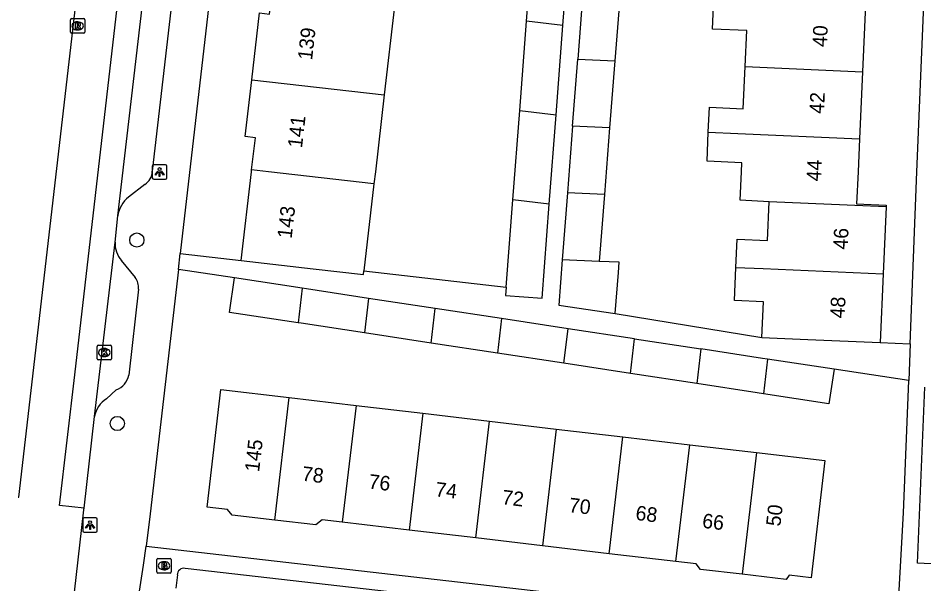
# Model space of a CAD drawing. Extents: x 162250 to 162654, y 380744 to 381605.
# Drawn here: x 162274.7 to 162337.1, y 380971.6 to 381010.6 of the extents above; entities that cross this region are included whole.
import ezdxf

# ---------------------------------------------------------------- set-up
doc = ezdxf.new("R2010")
doc.units = 0
for name, color, linetype in [('IMGEO_Boom', 7, 'Continuous'), ('IMGEO_Brandkraan', 7, 'Continuous'), ('IMGEO_Kolk', 7, 'Continuous'), ('IMGEO_Lichtpunt', 7, 'Continuous'), ('IMGEO_Pand', 7, 'Continuous'), ('IMGEO_Pand_nummerreeks', 7, 'Continuous'), ('IMGEO_Rijbaan_lokaal_gesloten', 7, 'Continuous'), ('IMGEO_Rioolput', 7, 'Continuous'), ('IMGEO_Voetpad_open', 7, 'Continuous')]:
    doc.layers.add(name, color=color, linetype=linetype)

msp = doc.modelspace()

# ---------------------------------------------------------------- linework, layer by layer
at = {"layer": 'IMGEO_Boom'}
for centre in [(162282.839, 380995.291), (162281.491, 380982.662)]:
    msp.add_circle(centre, 0.489, dxfattribs=at)
at = {"layer": 'IMGEO_Brandkraan'}
for p, q in [((162284.213, 380972.443), (162284.213, 380973.295)), ((162284.288, 380973.369), (162285.14, 380973.369)), ((162285.214, 380973.295), (162285.214, 380972.443)), ((162284.701, 380973.149), (162284.726, 380973.149)), ((162285.14, 380972.369), (162284.288, 380972.369)), ((162284.724, 380972.589), (162284.699, 380972.589))]:
    msp.add_line(p, q, dxfattribs=at)
for points in [[(162284.213, 380972.443), (162284.213, 380973.295)], [(162284.288, 380973.369), (162285.14, 380973.369)], [(162285.214, 380973.295), (162285.214, 380972.443)], [(162284.561, 380973.069), (162284.561, 380972.669), (162284.774, 380972.669)], [(162284.792, 380973.069), (162284.561, 380973.069)], [(162284.74, 380972.988), (162284.686, 380972.988), (162284.686, 380972.912)], [(162284.686, 380972.912), (162284.739, 380972.912)], [(162284.748, 380972.836), (162284.686, 380972.836), (162284.686, 380972.755)], [(162284.686, 380972.755), (162284.748, 380972.755)], [(162285.14, 380972.369), (162284.288, 380972.369)]]:
    msp.add_lwpolyline(points, dxfattribs=at)
for centre, radius, start, end in [((162284.29, 380973.293), 0.0765, 91.55205, 178.44795), ((162284.29, 380973.293), 0.0765, 91.55205, 178.44795), ((162285.138, 380973.293), 0.0765, 1.55205, 88.44795), ((162285.138, 380973.293), 0.0765, 1.55205, 88.44795), ((162284.741, 380972.95), 0.0379, 267.82845, 90.93552), ((162284.749, 380972.795), 0.0404, 269.87594, 90.50774), ((162284.78, 380972.92), 0.251, 268.66757, 293.53466), ((162284.796, 380972.924), 0.145, 59.4692, 91.53667), ((162284.821, 380972.971), 0.0922, 285.51372, 58.15012), ((162284.826, 380972.779), 0.105, 301.31148, 78.98903), ((162284.29, 380972.445), 0.0765, 181.55205, 268.44795), ((162284.29, 380972.445), 0.0765, 181.55205, 268.44795), ((162285.138, 380972.445), 0.0765, 271.55205, 358.44795), ((162285.138, 380972.445), 0.0765, 271.55205, 358.44795)]:
    msp.add_arc(centre, radius, start, end, dxfattribs=at)
for centre, major_axis, ratio, start_param, end_param in [((162284.7, 380972.869), (-0.387, 0.002), 0.722429, 4.712389, 7.853982), ((162284.725, 380972.869), (-0.39, 0.002), 0.717154, 1.570796, 4.712389)]:
    msp.add_ellipse(centre, major_axis=major_axis, ratio=ratio, start_param=start_param, end_param=end_param, dxfattribs=at)
at = {"layer": 'IMGEO_Kolk'}
for p, q in [((162280.096, 380987.12), (162280.096, 380987.972)), ((162280.171, 380988.046), (162281.023, 380988.046)), ((162280.584, 380987.826), (162280.609, 380987.826)), ((162281.097, 380987.972), (162281.097, 380987.12)), ((162281.023, 380987.046), (162280.171, 380987.046)), ((162280.607, 380987.266), (162280.582, 380987.266))]:
    msp.add_line(p, q, dxfattribs=at)
for points in [[(162280.096, 380987.12), (162280.096, 380987.972)], [(162280.171, 380988.046), (162281.023, 380988.046)], [(162280.417, 380987.746), (162280.54, 380987.746), (162280.54, 380987.595), (162280.67, 380987.746), (162280.834, 380987.746), (162280.688, 380987.595), (162280.841, 380987.346), (162280.689, 380987.346), (162280.604, 380987.51), (162280.54, 380987.443), (162280.54, 380987.346), (162280.417, 380987.346), (162280.417, 380987.746)], [(162281.097, 380987.972), (162281.097, 380987.12)], [(162281.023, 380987.046), (162280.171, 380987.046)]]:
    msp.add_lwpolyline(points, dxfattribs=at)
for centre, start, end in [((162280.173, 380987.97), 91.55205, 178.44795), ((162280.173, 380987.97), 91.55205, 178.44795), ((162281.021, 380987.97), 1.55205, 88.44795), ((162281.021, 380987.97), 1.55205, 88.44795), ((162280.173, 380987.122), 181.55205, 268.44795), ((162280.173, 380987.122), 181.55205, 268.44795), ((162281.021, 380987.122), 271.55205, 358.44795), ((162281.021, 380987.122), 271.55205, 358.44795)]:
    msp.add_arc(centre, 0.0765, start, end, dxfattribs=at)
for centre, major_axis, ratio, start_param, end_param in [((162280.583, 380987.546), (-0.387, 0.002), 0.722429, 4.712389, 7.853982), ((162280.608, 380987.546), (-0.39, 0.002), 0.717154, 1.570796, 4.712389)]:
    msp.add_ellipse(centre, major_axis=major_axis, ratio=ratio, start_param=start_param, end_param=end_param, dxfattribs=at)
at = {"layer": 'IMGEO_Lichtpunt'}
for p, q in [((162283.907, 381000.381), (162283.907, 380999.574)), ((162283.907, 381000.381), (162283.907, 380999.574)), ((162284.809, 381000.476), (162284.001, 381000.476)), ((162284.809, 381000.476), (162284.001, 381000.476)), ((162284.903, 380999.574), (162284.903, 381000.381)), ((162284.903, 380999.574), (162284.903, 381000.381)), ((162284.001, 380999.48), (162284.809, 380999.48)), ((162284.001, 380999.48), (162284.809, 380999.48)), ((162279.118, 380976.071), (162279.118, 380975.264)), ((162279.118, 380976.071), (162279.118, 380975.264)), ((162280.02, 380976.166), (162279.212, 380976.166)), ((162280.02, 380976.166), (162279.212, 380976.166)), ((162280.114, 380975.264), (162280.114, 380976.071)), ((162280.114, 380975.264), (162280.114, 380976.071)), ((162279.212, 380975.17), (162280.02, 380975.17)), ((162279.212, 380975.17), (162280.02, 380975.17))]:
    msp.add_line(p, q, dxfattribs=at)
for points in [[(162284.281, 381000.045), (162284.32, 381000.017), (162284.132, 380999.755), (162284.094, 380999.782), (162284.281, 381000.045)], [(162284.383, 380999.997), (162284.43, 380999.997), (162284.43, 380999.675), (162284.383, 380999.675), (162284.383, 380999.997)], [(162284.493, 381000.017), (162284.531, 381000.044), (162284.718, 380999.782), (162284.679, 380999.754), (162284.493, 381000.017)], [(162279.492, 380975.735), (162279.531, 380975.707), (162279.343, 380975.445), (162279.305, 380975.472), (162279.492, 380975.735)], [(162279.594, 380975.687), (162279.641, 380975.687), (162279.641, 380975.365), (162279.594, 380975.365), (162279.594, 380975.687)], [(162279.704, 380975.707), (162279.742, 380975.734), (162279.929, 380975.472), (162279.89, 380975.444), (162279.704, 380975.707)]]:
    msp.add_lwpolyline(points, dxfattribs=at)
for centre in [(162284.406, 381000.179), (162279.617, 380975.869)]:
    msp.add_circle(centre, 0.0994, dxfattribs=at)
for centre, start, end in [((162284.001, 381000.381), 90, 180), ((162284.001, 381000.381), 90, 180), ((162284.809, 381000.381), 0, 90), ((162284.809, 381000.381), 0, 90), ((162284.001, 380999.574), 180, 270), ((162284.001, 380999.574), 180, 270), ((162284.809, 380999.574), 270, 0), ((162284.809, 380999.574), 270, 360), ((162279.212, 380976.071), 90, 180), ((162279.212, 380976.071), 90, 180), ((162280.02, 380976.071), 0, 90), ((162280.02, 380976.071), 0, 90), ((162279.212, 380975.264), 180, 270), ((162279.212, 380975.264), 180, 270), ((162280.02, 380975.264), 270, 0), ((162280.02, 380975.264), 270, 360)]:
    msp.add_arc(centre, 0.0946, start, end, dxfattribs=at)
at = {"layer": 'IMGEO_Pand'}
for points in [[(162309.705, 381010.356), (162310.176, 381016.505)], [(162312.206, 381010.067), (162312.677, 381016.217)], [(162290.767, 381006.335), (162291.297, 381010.932), (162291.982, 381010.853), (162292.158, 381012.378)], [(162313.582, 381012.347), (162313.226, 381007.744)], [(162316.153, 381012.234), (162315.79, 381007.631)], [(162300.593, 381011.406), (162299.888, 381005.284)], [(162324.768, 381007.236), (162324.877, 381009.717), (162322.506, 381009.821), (162322.599, 381011.95)], [(162333.051, 381011.491), (162332.848, 381006.881)], [(162309.234, 381004.207), (162309.705, 381010.356)], [(162312.206, 381010.067), (162309.705, 381010.356)], [(162311.735, 381003.918), (162312.206, 381010.067)], [(162312.87, 381003.14), (162313.226, 381007.744)], [(162313.226, 381007.744), (162315.79, 381007.631)], [(162315.79, 381007.631), (162315.428, 381003.027)], [(162322.227, 381002.729), (162322.302, 381004.441), (162324.64, 381004.338), (162324.768, 381007.236)], [(162324.768, 381007.236), (162332.848, 381006.881)], [(162332.848, 381006.881), (162332.645, 381002.27)], [(162290.753, 381000.133), (162291.008, 381002.341), (162290.316, 381002.42), (162290.767, 381006.335)], [(162290.767, 381006.335), (162299.888, 381005.284)], [(162299.888, 381005.284), (162299.279, 381000), (162299.182, 380999.162)], [(162308.763, 380998.057), (162309.234, 381004.207)], [(162309.234, 381004.207), (162311.735, 381003.918)], [(162311.264, 380997.769), (162311.735, 381003.918)], [(162312.87, 381003.14), (162312.515, 380998.537)], [(162315.428, 381003.027), (162312.87, 381003.14)], [(162315.428, 381003.027), (162315.065, 380998.425)], [(162326.421, 380997.925), (162324.43, 380998.033), (162324.516, 381000), (162324.543, 381000.615), (162322.138, 381000.721), (162322.227, 381002.729)], [(162322.227, 381002.729), (162324.267, 381002.639), (162332.645, 381002.27)], [(162332.645, 381002.27), (162332.545, 381000), (162332.448, 380997.793), (162334.488, 380997.703), (162334.482, 380997.57)], [(162290.035, 380993.891), (162290.738, 381000), (162290.753, 381000.133)], [(162299.182, 380999.162), (162291.908, 381000), (162290.753, 381000.133)], [(162299.182, 380999.162), (162298.492, 380993.175)], [(162312.515, 380998.537), (162312.159, 380993.933)], [(162315.065, 380998.425), (162312.515, 380998.537)], [(162315.065, 380998.425), (162314.703, 380993.821)], [(162308.303, 380992.045), (162308.26, 380991.48), (162310.768, 380991.288), (162311.264, 380997.769)], [(162308.303, 380992.045), (162308.763, 380998.057)], [(162311.264, 380997.769), (162308.763, 380998.057)], [(162324.127, 380993.406), (162324.213, 380995.35), (162326.304, 380995.258), (162326.421, 380997.925)], [(162334.482, 380997.57), (162326.421, 380997.925)], [(162334.482, 380997.57), (162334.279, 380992.96)], [(162290.035, 380993.891), (162295.003, 380993.319), (162298.463, 380992.92), (162298.492, 380993.175)], [(162312.159, 380993.933), (162311.918, 380990.819), (162315.801, 380990.225)], [(162314.703, 380993.821), (162312.159, 380993.933)], [(162315.801, 380990.225), (162316.026, 380993.053), (162316.083, 380993.76), (162314.703, 380993.821)], [(162325.921, 380988.589), (162326.029, 380991.043), (162324.027, 380991.131), (162324.127, 380993.406)], [(162324.127, 380993.406), (162326.001, 380993.324), (162334.279, 380992.96)], [(162293.955, 380989.594), (162289.217, 380990.315), (162289.578, 380992.684)], [(162294.235, 380991.976), (162289.578, 380992.684)], [(162334.279, 380992.96), (162334.071, 380988.231)], [(162294.235, 380991.976), (162293.955, 380989.594)], [(162298.815, 380991.279), (162294.522, 380991.932), (162294.235, 380991.976)], [(162298.815, 380991.279), (162298.535, 380988.897)], [(162303.395, 380990.582), (162298.815, 380991.279)], [(162303.115, 380988.2), (162303.395, 380990.582)], [(162307.978, 380989.884), (162303.395, 380990.582)], [(162298.535, 380988.897), (162294.161, 380989.563), (162293.955, 380989.594)], [(162307.978, 380989.884), (162307.698, 380987.503)], [(162312.557, 380989.187), (162307.978, 380989.884)], [(162303.115, 380988.2), (162298.535, 380988.897)], [(162312.278, 380986.806), (162312.557, 380989.187)], [(162317.138, 380988.49), (162312.557, 380989.187)], [(162316.858, 380986.109), (162317.138, 380988.49)], [(162317.138, 380988.49), (162321.721, 380987.792)], [(162325.921, 380988.589), (162329.076, 380988.45), (162334.071, 380988.231)], [(162307.698, 380987.503), (162303.115, 380988.2)], [(162321.721, 380987.792), (162321.44, 380985.411)], [(162326.301, 380987.095), (162325.955, 380987.148), (162321.721, 380987.792)], [(162312.278, 380986.806), (162307.698, 380987.503)], [(162326.301, 380987.095), (162326.021, 380984.714)], [(162330.898, 380986.396), (162326.301, 380987.095)], [(162316.858, 380986.109), (162312.278, 380986.806)], [(162330.898, 380986.396), (162330.538, 380984.027), (162326.021, 380984.714)], [(162321.44, 380985.411), (162316.858, 380986.109)], [(162326.021, 380984.714), (162325.595, 380984.779), (162321.44, 380985.411)], [(162292.357, 380976.007), (162289.405, 380976.354), (162289.096, 380976.745), (162287.68, 380976.912), (162288.631, 380984.999), (162293.349, 380984.444)], [(162292.357, 380976.007), (162293.349, 380984.444)], [(162293.349, 380984.444), (162297.948, 380983.904)], [(162297.948, 380983.904), (162297.003, 380975.862)], [(162297.948, 380983.904), (162302.547, 380983.363)], [(162302.547, 380983.363), (162301.602, 380975.321)], [(162302.547, 380983.363), (162307.147, 380982.822)], [(162306.201, 380974.781), (162307.147, 380982.822)], [(162307.147, 380982.822), (162311.746, 380982.282)], [(162311.746, 380982.282), (162310.801, 380974.24)], [(162311.746, 380982.282), (162316.345, 380981.741)], [(162315.4, 380973.699), (162316.345, 380981.741)], [(162316.345, 380981.741), (162320.945, 380981.2)], [(162319.999, 380973.159), (162320.945, 380981.2)], [(162320.945, 380981.2), (162325.544, 380980.66)], [(162325.544, 380980.66), (162330.262, 380980.105), (162329.314, 380972.033), (162327.806, 380972.21), (162327.594, 380971.925), (162324.559, 380972.282)], [(162325.544, 380980.66), (162324.559, 380972.282)], [(162297.003, 380975.862), (162295.616, 380976.025), (162295.174, 380975.676), (162292.357, 380976.007)], [(162301.602, 380975.321), (162297.003, 380975.862)], [(162306.201, 380974.781), (162301.602, 380975.321)], [(162310.801, 380974.24), (162306.201, 380974.781)], [(162315.4, 380973.699), (162310.801, 380974.24)], [(162319.999, 380973.159), (162315.4, 380973.699)], [(162324.559, 380972.282), (162321.687, 380972.62), (162321.391, 380972.995), (162319.999, 380973.159)]]:
    msp.add_lwpolyline(points, dxfattribs=at)
at = {"layer": 'IMGEO_Rijbaan_lokaal_gesloten'}
for points in [[(162274.657, 380977.597), (162274.701, 380977.591), (162290.278, 381112.181)], [(162279.203, 380976.84), (162277.507, 380977.016), (162278.556, 380986.022), (162293.089, 381111.897)], [(162281.526, 380996.953), (162287.288, 381046.38)], [(162281.338, 380995.138), (162281.526, 380996.953)], [(162279.928, 380983.133), (162281.338, 380995.138)], [(162279.203, 380976.84), (162279.928, 380983.133)], [(162277.356, 380960.724), (162278.069, 380966.836), (162278.655, 380972.068), (162279.19, 380976.722), (162279.196, 380976.775), (162279.203, 380976.84)]]:
    msp.add_lwpolyline(points, dxfattribs=at)
at = {"layer": 'IMGEO_Rioolput'}
for p, q in [((162278.259, 381009.609), (162278.259, 381010.461)), ((162278.334, 381010.535), (162279.186, 381010.535)), ((162278.747, 381010.315), (162278.772, 381010.315)), ((162279.26, 381010.461), (162279.26, 381009.609)), ((162279.186, 381009.535), (162278.334, 381009.535)), ((162278.77, 381009.755), (162278.745, 381009.755))]:
    msp.add_line(p, q, dxfattribs=at)
for points in [[(162278.259, 381009.609), (162278.259, 381010.461)], [(162278.334, 381010.535), (162279.186, 381010.535)], [(162278.848, 381010.233), (162278.596, 381010.235), (162278.596, 381009.835)], [(162278.774, 381010.154), (162278.72, 381010.154), (162278.72, 381010.073)], [(162279.26, 381010.461), (162279.26, 381009.609)], [(162279.186, 381009.535), (162278.334, 381009.535)], [(162278.596, 381009.835), (162278.72, 381009.835), (162278.72, 381009.997), (162278.731, 381009.997)], [(162278.72, 381010.073), (162278.772, 381010.073)], [(162278.778, 381009.968), (162278.849, 381009.835), (162278.989, 381009.835), (162278.924, 381009.961)]]:
    msp.add_lwpolyline(points, dxfattribs=at)
for centre, radius, start, end in [((162278.336, 381010.459), 0.0765, 91.55205, 178.44795), ((162278.336, 381010.459), 0.0765, 91.55205, 178.44795), ((162278.78, 381010.058), 0.0964, 77.00612, 93.18647), ((162278.794, 381010.115), 0.0378, 276.66336, 79.67722), ((162278.847, 381010.123), 0.109, 350.36119, 89.41601), ((162278.845, 381010.123), 0.112, 277.58423, 350.98172), ((162279.184, 381010.459), 0.0765, 1.55205, 88.44795), ((162279.184, 381010.459), 0.0765, 1.55205, 88.44795), ((162278.336, 381009.611), 0.0765, 181.55205, 268.44795), ((162278.336, 381009.611), 0.0765, 181.55205, 268.44795), ((162278.73, 381009.944), 0.0533, 26.02933, 88.69889), ((162278.756, 381010.262), 0.19, 274.7715, 282.96867), ((162278.829, 381009.908), 0.108, 29.51342, 73.79051), ((162279.184, 381009.611), 0.0765, 271.55205, 358.44795), ((162279.184, 381009.611), 0.0765, 271.55205, 358.44795)]:
    msp.add_arc(centre, radius, start, end, dxfattribs=at)
for centre, major_axis, ratio, start_param, end_param in [((162278.746, 381010.035), (-0.387, 0.002), 0.722429, 4.712389, 7.853982), ((162278.771, 381010.035), (-0.39, 0.002), 0.717154, 1.570796, 4.712389)]:
    msp.add_ellipse(centre, major_axis=major_axis, ratio=ratio, start_param=start_param, end_param=end_param, dxfattribs=at)
at = {"layer": 'IMGEO_Voetpad_open'}
for points in [[(162297.87, 381098.686), (162285.829, 380994.375)], [(162336.141, 380988.151), (162336.6, 381000), (162337.62, 381024.184), (162335.584, 381024.354), (162336.016, 381034.263), (162338.044, 381034.203), (162340.701, 381094.418)], [(162288.884, 381043.029), (162283.902, 381000.035)], [(162283.385, 380999.117), (162282.275, 380998.252)], [(162281.771, 380993.896), (162282.719, 380992.708)], [(162285.702, 380993.275), (162285.829, 380994.375)], [(162285.829, 380994.375), (162290.035, 380993.891)], [(162285.702, 380993.275), (162283.759, 380976.44), (162283.492, 380974.216)], [(162289.578, 380992.684), (162285.702, 380993.275)], [(162298.492, 380993.175), (162308.303, 380992.045)], [(162282.952, 380991.919), (162282.278, 380986)], [(162315.801, 380990.225), (162325.921, 380988.589)], [(162334.071, 380988.231), (162336.141, 380988.151)], [(162336.141, 380988.151), (162336.042, 380985.614)], [(162336.042, 380985.614), (162330.898, 380986.396)], [(162335.219, 380968.294), (162335.689, 380976.508), (162336.042, 380985.614)], [(162338.509, 380972.948), (162336.646, 380973.052), (162337.162, 380985.171)], [(162281.425, 380984.97), (162280.742, 380984.365)], [(162283.032, 380971.129), (162283.298, 380972.915), (162283.492, 380974.216)], [(162283.492, 380974.216), (162335.219, 380968.294)], [(162332.037, 380967.44), (162286.174, 380972.683)], [(162285.631, 380972.233), (162285.538, 380971.317)]]:
    msp.add_lwpolyline(points, dxfattribs=at)
for centre, radius, start, end in [((162282.815, 381000.043), 1.087, 301.63438, 359.59087), ((162283.475, 380996.694), 1.966, 127.62018, 172.44455), ((162283.124, 380995.064), 1.787, 177.63071, 220.80959), ((162281.934, 380992.047), 1.026, 352.81851, 40.08634), ((162280.923, 380986.254), 1.379, 291.36214, 349.37779), ((162281.715, 380982.837), 1.812, 122.49855, 170.59483), ((162286.081, 380972.242), 0.451, 78.14518, 181.1539)]:
    msp.add_arc(centre, radius, start, end, dxfattribs=at)

# ---------------------------------------------------------------- texts
at = {"layer": 'IMGEO_Pand_nummerreeks'}
for s, rotation, p in [('139', 83.44983, (162294.916, 381007.644)), ('40', 87.48029, (162330.399, 381008.569)), ('42', 87.48029, (162330.197, 381003.968)), ('141', 83.44983, (162294.221, 381001.595)), ('44', 87.48046, (162329.993, 380999.318)), ('143', 83.43411, (162293.505, 380995.358)), ('46', 87.47921, (162331.83, 380994.621)), ('48', 87.47921, (162331.621, 380989.888)), ('145', 83.29304, (162291.264, 380979.294)), ('78', 353.29532, (162294.18, 380978.73)), ('76', 353.29532, (162298.776, 380978.191)), ('74', 353.29532, (162303.375, 380977.65)), ('72', 353.29532, (162307.972, 380977.109)), ('70', 353.29532, (162312.577, 380976.568)), ('68', 353.29532, (162317.176, 380976.027)), ('50', 83.30169, (162327.19, 380975.545)), ('66', 353.29532, (162321.772, 380975.487))]:
    msp.add_text(s, height=1, rotation=rotation, dxfattribs=at).set_placement(p)

doc.saveas('drawing.dxf')
